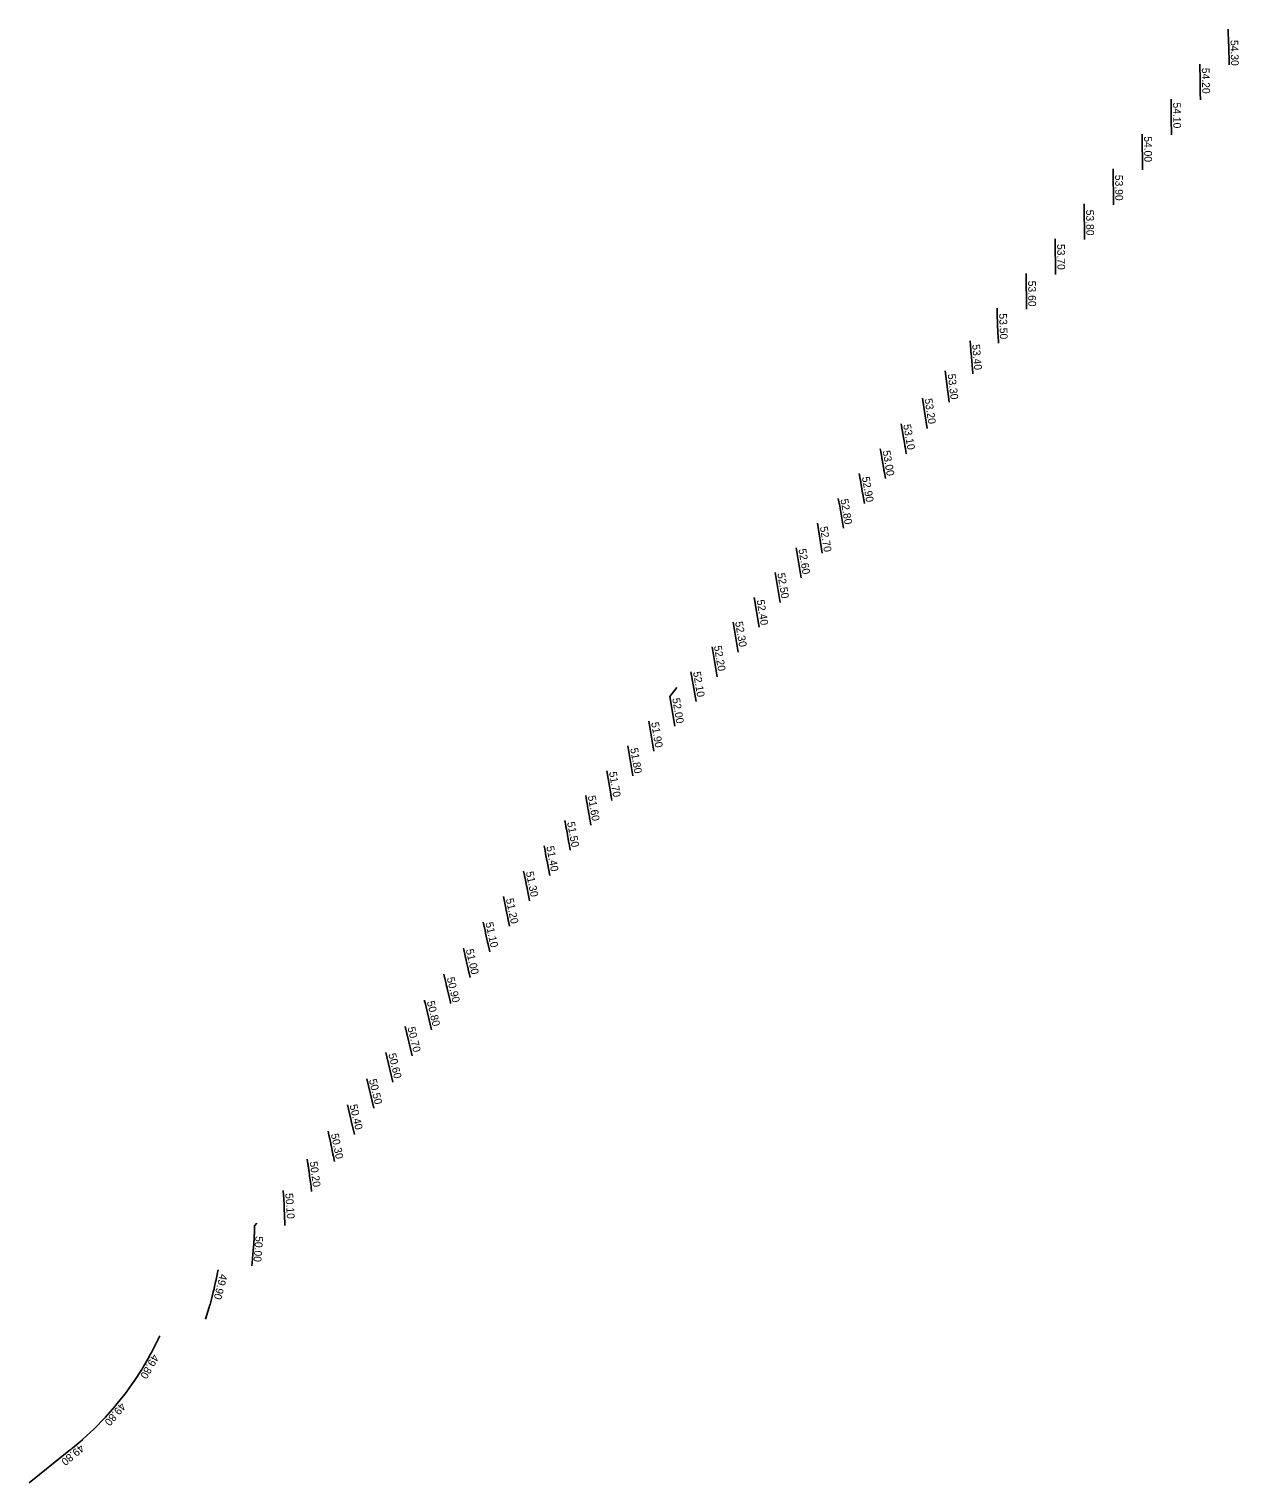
# Model space of a CAD drawing. Extents: x 655100 to 703495, y 6445581 to 6476602.
# Drawn here: x 668343.3 to 668500.1, y 6466113.1 to 6466301.4 of the extents above; entities that cross this region are included whole.
import ezdxf

# ---------------------------------------------------------------- set-up
doc = ezdxf.new("R2010")
doc.units = 0
for name, color, linetype in [('horis_01', 7, 'Continuous'), ('horis_1', 7, 'Continuous'), ('horis_korgusarv', 7, 'Continuous')]:
    doc.layers.add(name, color=color, linetype=linetype)

msp = doc.modelspace()

# ---------------------------------------------------------------- linework, layer by layer
at = {"layer": 'horis_01'}
for points in [[(668498.81, 6466296.81), (668498.81, 6466296.86), (668498.75, 6466299.25), (668498.75, 6466299.31), (668498.75, 6466299.48), (668498.74, 6466299.53), (668498.69, 6466301.44)], [(668495.09, 6466292.26), (668495.07, 6466293.15), (668495.07, 6466293.29), (668495.07, 6466293.43), (668495.06, 6466293.57), (668495.06, 6466293.72), (668495.05, 6466294.56), (668495.04, 6466294.67), (668495.04, 6466294.77), (668495.04, 6466294.79), (668495, 6466296.89)], [(668491.28, 6466292.35), (668491.31, 6466290.07), (668491.31, 6466290.03), (668491.31, 6466289.81), (668491.34, 6466287.72)], [(668483.82, 6466278.69), (668483.77, 6466283.32)], [(668480.07, 6466274.17), (668480.02, 6466278.8)], [(668476.31, 6466269.66), (668476.26, 6466274.28)], [(668472.55, 6466265.14), (668472.5, 6466269.77)], [(668468.75, 6466265.26), (668468.76, 6466264.68), (668468.76, 6466264.64), (668468.76, 6466264.59), (668468.76, 6466264.55), (668468.77, 6466264.5), (668468.85, 6466262.06), (668468.85, 6466261.99), (668468.85, 6466261.92), (668468.86, 6466261.84), (668468.86, 6466261.77), (668468.91, 6466260.76)], [(668465.59, 6466256.77), (668465.58, 6466256.83), (668465.58, 6466256.84), (668465.36, 6466259.45), (668465.35, 6466259.54), (668465.34, 6466259.64), (668465.33, 6466259.73), (668465.33, 6466259.82), (668465.24, 6466261.04)], [(668462.54, 6466253.1), (668462.39, 6466254.17), (668462.39, 6466254.23), (668462.38, 6466254.3), (668462.37, 6466254.36), (668462.36, 6466254.42), (668462.03, 6466257.18)], [(668459.07, 6466253.62), (668459.38, 6466251.59), (668459.38, 6466251.58), (668459.69, 6466249.68)], [(668456.3, 6466250.28), (668456.38, 6466249.83), (668456.4, 6466249.68), (668456.43, 6466249.52), (668456.56, 6466248.77), (668456.58, 6466248.69), (668456.61, 6466248.51), (668456.62, 6466248.46), (668456.64, 6466248.35), (668456.65, 6466248.32), (668456.79, 6466247.53), (668456.8, 6466247.42), (668456.82, 6466247.31), (668456.84, 6466247.2), (668456.86, 6466247.09), (668456.98, 6466246.42)], [(668450.89, 6466243.84), (668451.01, 6466243.14), (668451.03, 6466243.03), (668451.05, 6466242.91), (668451.07, 6466242.8), (668451.09, 6466242.68), (668451.32, 6466241.31), (668451.34, 6466241.21), (668451.36, 6466241.11), (668451.38, 6466241.01), (668451.39, 6466240.91), (668451.55, 6466239.97)], [(668448.17, 6466240.63), (668448.25, 6466240.18), (668448.27, 6466240.03), (668448.3, 6466239.88), (668448.82, 6466236.76)], [(668445.45, 6466237.42), (668446.09, 6466233.55)], [(668443.37, 6466230.34), (668442.72, 6466234.21)], [(668439.99, 6466231.01), (668440.64, 6466227.14)], [(668437.26, 6466227.8), (668437.91, 6466223.93)], [(668434.54, 6466224.59), (668435.19, 6466220.72)], [(668432.46, 6466217.51), (668431.81, 6466221.38)], [(668429.08, 6466218.17), (668429.73, 6466214.31)], [(668424.28, 6466207.89), (668423.63, 6466211.76)], [(668420.9, 6466208.55), (668421.55, 6466204.68)], [(668418.82, 6466201.48), (668418.73, 6466201.99), (668418.72, 6466202.08), (668418.71, 6466202.16), (668418.69, 6466202.25), (668418.68, 6466202.33), (668418.17, 6466205.34)], [(668415.44, 6466202.13), (668415.6, 6466201.23), (668415.62, 6466201.12), (668415.63, 6466201.02), (668415.65, 6466200.92), (668415.67, 6466200.81), (668415.76, 6466200.28), (668415.77, 6466200.24), (668415.78, 6466200.2), (668415.78, 6466200.15), (668415.79, 6466200.11), (668415.82, 6466199.93), (668415.83, 6466199.88), (668415.84, 6466199.84), (668415.85, 6466199.79), (668415.85, 6466199.75), (668415.91, 6466199.41), (668415.93, 6466199.34), (668415.94, 6466199.27), (668415.95, 6466199.2), (668415.96, 6466199.13), (668416.12, 6466198.27)], [(668412.73, 6466198.89), (668412.86, 6466198.22), (668412.88, 6466198.1), (668412.9, 6466197.99), (668412.92, 6466197.88), (668412.94, 6466197.77), (668413.06, 6466197.11), (668413.07, 6466197.03), (668413.08, 6466196.96), (668413.1, 6466196.88), (668413.11, 6466196.81), (668413.17, 6466196.51), (668413.18, 6466196.43), (668413.19, 6466196.36), (668413.21, 6466196.28), (668413.22, 6466196.21), (668413.32, 6466195.67), (668413.33, 6466195.61), (668413.34, 6466195.54), (668413.36, 6466195.48), (668413.37, 6466195.42), (668413.44, 6466195.03)], [(668410.79, 6466191.78), (668410.48, 6466193.38), (668410.47, 6466193.44), (668410.44, 6466193.58), (668410.43, 6466193.62), (668410.42, 6466193.7), (668410.41, 6466193.73), (668410.25, 6466194.56), (668410.23, 6466194.66), (668410.21, 6466194.77), (668410.19, 6466194.88), (668410.17, 6466194.99), (668410.05, 6466195.63)], [(668408.17, 6466188.5), (668407.8, 6466190.33), (668407.77, 6466190.44), (668407.77, 6466190.47), (668407.58, 6466191.43), (668407.56, 6466191.52), (668407.54, 6466191.61), (668407.52, 6466191.7), (668407.5, 6466191.8), (668407.4, 6466192.34)], [(668405.57, 6466185.2), (668405.43, 6466185.86), (668405.41, 6466185.97), (668405.39, 6466186.08), (668405.36, 6466186.19), (668405.34, 6466186.3), (668405.17, 6466187.08), (668405.16, 6466187.13), (668405.14, 6466187.24), (668405.13, 6466187.29), (668405.1, 6466187.45), (668405.09, 6466187.5), (668405.08, 6466187.53), (668404.77, 6466189.04)], [(668402.17, 6466185.71), (668402.4, 6466184.64), (668402.42, 6466184.56), (668402.44, 6466184.47), (668402.46, 6466184.39), (668402.47, 6466184.3), (668402.73, 6466183.11), (668402.76, 6466182.99), (668402.78, 6466182.88), (668402.81, 6466182.76), (668402.83, 6466182.65), (668403.01, 6466181.88)], [(668397.06, 6466178.99), (668397.16, 6466178.54), (668397.18, 6466178.46), (668397.2, 6466178.39), (668397.21, 6466178.32), (668397.23, 6466178.24), (668397.35, 6466177.71), (668397.37, 6466177.65), (668397.38, 6466177.58), (668397.4, 6466177.52), (668397.41, 6466177.46), (668397.47, 6466177.2), (668397.49, 6466177.14), (668397.5, 6466177.08), (668397.52, 6466177.01), (668397.53, 6466176.95), (668397.62, 6466176.58), (668397.64, 6466176.5), (668397.66, 6466176.41), (668397.68, 6466176.33), (668397.7, 6466176.25), (668397.91, 6466175.35), (668397.94, 6466175.25), (668397.96, 6466175.17)], [(668395.46, 6466171.78), (668394.62, 6466175.28), (668394.6, 6466175.36), (668394.57, 6466175.47), (668394.56, 6466175.51), (668394.54, 6466175.6)], [(668392.05, 6466172.2), (668392.97, 6466168.39)], [(668389.55, 6466168.81), (668390.47, 6466165)], [(668387.06, 6466165.42), (668387.97, 6466161.61)], [(668384.56, 6466162.03), (668385.04, 6466160.04), (668385.06, 6466159.98), (668385.48, 6466158.22)], [(668382.87, 6466154.69), (668382.74, 6466155.38), (668382.71, 6466155.5), (668382.69, 6466155.62), (668382.67, 6466155.73), (668382.64, 6466155.85), (668382.49, 6466156.65), (668382.48, 6466156.69), (668382.46, 6466156.78), (668382.45, 6466156.81), (668382.45, 6466156.83), (668382.43, 6466156.93), (668382.42, 6466156.95), (668382.42, 6466156.97), (668382.42, 6466157), (668382.41, 6466157.02), (668382.23, 6466157.81), (668382.21, 6466157.89), (668382.2, 6466157.97), (668382.18, 6466158.05), (668382.16, 6466158.13), (668382.05, 6466158.62)], [(668379.34, 6466154.99), (668379.44, 6466154.39), (668379.46, 6466154.29), (668379.48, 6466154.19), (668379.49, 6466154.09), (668379.51, 6466153.99), (668379.61, 6466153.24), (668379.63, 6466153.08), (668379.65, 6466152.92), (668379.67, 6466152.76), (668379.69, 6466152.6), (668379.85, 6466151.46), (668379.85, 6466151.42), (668379.86, 6466151.38), (668379.86, 6466151.34), (668379.86, 6466151.3), (668379.88, 6466151.12), (668379.89, 6466151.09), (668379.89, 6466151.06), (668379.89, 6466151.02), (668379.9, 6466150.99), (668379.92, 6466150.8)], [(668376.46, 6466146.41), (668376.45, 6466146.64), (668376.45, 6466146.69), (668376.39, 6466148.66), (668376.39, 6466148.73), (668376.39, 6466148.8), (668376.38, 6466148.94), (668376.38, 6466148.98), (668376.38, 6466149.01), (668376.37, 6466149.05), (668376.37, 6466149.09), (668376.32, 6466149.86), (668376.31, 6466149.97), (668376.31, 6466150.08), (668376.3, 6466150.19), (668376.29, 6466150.3), (668376.24, 6466150.97)], [(668366.17, 6466134.26), (668366.65, 6466135.83), (668366.71, 6466136), (668366.76, 6466136.18), (668366.81, 6466136.36), (668366.86, 6466136.54), (668367.09, 6466137.45), (668367.12, 6466137.54), (668367.14, 6466137.63), (668367.16, 6466137.72), (668367.19, 6466137.81), (668367.28, 6466138.17), (668367.3, 6466138.26), (668367.32, 6466138.35), (668367.34, 6466138.44), (668367.36, 6466138.53), (668367.48, 6466139.1), (668367.51, 6466139.23), (668367.54, 6466139.35), (668367.56, 6466139.48), (668367.59, 6466139.6), (668367.79, 6466140.56), (668367.79, 6466140.57), (668367.79, 6466140.58), (668367.8, 6466140.6), (668367.8, 6466140.61), (668367.81, 6466140.69)], [(668360.26, 6466132.13), (668360.02, 6466131.6), (668360, 6466131.56), (668359.98, 6466131.51), (668359.95, 6466131.46), (668359.93, 6466131.42), (668359.18, 6466129.97), (668359.1, 6466129.82), (668359.02, 6466129.68), (668358.94, 6466129.53), (668358.86, 6466129.39), (668358.09, 6466128.07), (668358.05, 6466127.99), (668358, 6466127.91), (668357.95, 6466127.84), (668357.91, 6466127.76), (668356.92, 6466126.24), (668356.91, 6466126.23), (668356.9, 6466126.21), (668356.89, 6466126.2), (668356.88, 6466126.18), (668355.75, 6466124.61), (668355.74, 6466124.59), (668355.73, 6466124.58), (668355.72, 6466124.56), (668355.71, 6466124.55), (668354.53, 6466123.07), (668354.51, 6466123.04), (668354.48, 6466123.01), (668354.46, 6466122.99), (668354.43, 6466122.96), (668353.21, 6466121.57), (668353.19, 6466121.54), (668353.16, 6466121.51), (668353.13, 6466121.48), (668353.1, 6466121.46), (668351.8, 6466120.12), (668351.78, 6466120.1), (668351.76, 6466120.08), (668351.74, 6466120.06), (668351.72, 6466120.04), (668350.3, 6466118.72), (668350.29, 6466118.71), (668350.28, 6466118.7), (668348.99, 6466117.62), (668348.86, 6466117.52), (668348.74, 6466117.41), (668348.62, 6466117.31), (668348.49, 6466117.21), (668343.32, 6466113.06)]]:
    msp.add_lwpolyline(points, dxfattribs=at)
at = {"layer": 'horis_1'}
for points in [[(668487.53, 6466287.83), (668487.58, 6466283.21)], [(668453.6, 6466247.05), (668453.66, 6466246.69), (668453.67, 6466246.63), (668453.68, 6466246.57), (668453.7, 6466246.51), (668453.71, 6466246.45), (668453.79, 6466245.98), (668453.8, 6466245.89), (668453.82, 6466245.81), (668453.83, 6466245.72), (668453.85, 6466245.64), (668454.06, 6466244.43), (668454.08, 6466244.32), (668454.1, 6466244.2), (668454.12, 6466244.09), (668454.14, 6466243.97), (668454.27, 6466243.19)], [(668426.35, 6466214.97), (668427.23, 6466216.11)], [(668426.35, 6466214.97), (668427, 6466211.1)], [(668400.47, 6466178.53), (668400.25, 6466179.46), (668400.23, 6466179.56), (668400.21, 6466179.66), (668400.19, 6466179.76), (668400.16, 6466179.85), (668400.05, 6466180.35), (668400.04, 6466180.4), (668400.03, 6466180.44), (668400.02, 6466180.49), (668400.01, 6466180.54), (668399.96, 6466180.73), (668399.95, 6466180.78), (668399.94, 6466180.83), (668399.93, 6466180.88), (668399.92, 6466180.93), (668399.82, 6466181.37), (668399.77, 6466181.58), (668399.7, 6466181.91), (668399.69, 6466181.96), (668399.68, 6466182), (668399.67, 6466182.05), (668399.66, 6466182.09), (668399.6, 6466182.36)], [(668372.54, 6466146.35), (668372.84, 6466146.73)], [(668372.54, 6466146.35), (668372.52, 6466145.64), (668372.51, 6466145.53), (668372.51, 6466145.41), (668372.51, 6466145.29), (668372.5, 6466145.18), (668372.48, 6466144.62), (668372.47, 6466144.54), (668372.47, 6466144.47), (668372.46, 6466144.39), (668372.46, 6466144.31), (668372.43, 6466143.99), (668372.43, 6466143.91), (668372.42, 6466143.83), (668372.41, 6466143.75), (668372.41, 6466143.68), (668372.28, 6466142.12), (668372.28, 6466142.07), (668372.27, 6466142.03), (668372.27, 6466141.98), (668372.26, 6466141.93), (668372.24, 6466141.74), (668372.23, 6466141.69), (668372.23, 6466141.64), (668372.22, 6466141.59), (668372.22, 6466141.54), (668372.17, 6466141.19)]]:
    msp.add_lwpolyline(points, dxfattribs=at)

# ---------------------------------------------------------------- texts
at = {"layer": 'horis_korgusarv'}
for s, rotation, p in [('54.30', 271.3602, (668498.98, 6466300.02)), ('54.20', 271.1734, (668495.26, 6466296.41)), ('54.10', 270.8296, (668491.53, 6466291.92)), ('54.00', 270.6472, (668487.78, 6466287.55)), ('53.90', 270.6472, (668484.03, 6466282.55)), ('53.80', 270.6472, (668480.27, 6466278.03)), ('53.70', 270.6472, (668476.52, 6466273.59)), ('53.60', 270.6472, (668472.76, 6466268.83)), ('53.50', 271.8995, (668469.01, 6466264.58)), ('53.40', 274.9456, (668465.51, 6466260.56)), ('53.30', 276.8137, (668462.34, 6466256.72)), ('53.20', 278.5616, (668459.34, 6466253.52)), ('53.10', 280.0621, (668456.57, 6466250.15)), ('53.00', 279.8787, (668453.9, 6466246.77)), ('52.90', 279.6495, (668451.23, 6466243.37)), ('52.80', 279.526, (668448.45, 6466240.49)), ('52.70', 279.526, (668445.78, 6466236.92)), ('52.60', 279.526, (668443, 6466234.03)), ('52.50', 279.526, (668440.26, 6466230.89)), ('52.40', 279.526, (668437.58, 6466227.43)), ('52.30', 279.526, (668434.79, 6466224.61)), ('52.20', 279.526, (668432.05, 6466221.48)), ('52.10', 279.526, (668429.34, 6466218.12)), ('52.00', 279.526, (668426.65, 6466214.69)), ('51.90', 279.526, (668423.91, 6466211.57)), ('51.80', 279.526, (668421.21, 6466208.22)), ('51.70', 279.526, (668418.46, 6466205.15)), ('51.60', 279.9093, (668415.71, 6466202.06)), ('51.50', 280.2336, (668413.03, 6466198.65)), ('51.40', 280.8261, (668410.33, 6466195.5)), ('51.30', 281.2844, (668407.68, 6466192.2)), ('51.20', 281.7514, (668405.09, 6466188.71)), ('51.10', 282.2738, (668402.44, 6466185.62)), ('51.00', 282.8068, (668399.9, 6466182.13)), ('50.90', 283.3303, (668397.43, 6466178.48)), ('50.80', 283.5475, (668394.85, 6466175.4)), ('50.70', 283.5475, (668392.34, 6466172.04)), ('50.60', 283.5475, (668389.86, 6466168.62)), ('50.50', 283.5475, (668387.35, 6466165.28)), ('50.40', 283.5475, (668384.83, 6466161.99)), ('50.30', 281.5701, (668382.42, 6466158.24)), ('50.20', 277.7803, (668379.67, 6466154.66)), ('50.10', 273.8314, (668376.52, 6466150.58)), ('50.00', 265.4796, (668372.66, 6466145.07)), ('49.90', 255.4475, (668368.07, 6466140.21)), ('49.80', 239.9039, (668359.35, 6466129.82)), ('49.80', 229.466, (668355.2, 6466123.54)), ('49.80', 219.4398, (668349.97, 6466118.12))]:
    msp.add_text(s, height=1, rotation=rotation, dxfattribs=at).set_placement(p)

doc.saveas('drawing.dxf')
